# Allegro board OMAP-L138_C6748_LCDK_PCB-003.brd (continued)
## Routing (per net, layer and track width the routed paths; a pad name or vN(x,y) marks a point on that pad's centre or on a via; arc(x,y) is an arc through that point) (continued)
LCD_SDA: length 32.2
  TOP w0.121: U25.4 22.66,60.5 v1(22.86,60.71)
  LYR3 w0.133: P1.15 5.59,68.96 5.59,70.61 6.6,71.63 9.4,71.63 9.91,71.12 11.94,71.12 12.95,70.1 12.95,69.09 15.49,66.55 16.51,66.55 18.8,64.26 22.61,64.26 23.37,63.5 23.37,62.48 23.88,61.98 24.38,61.98 24.64,61.72 24.64,60.45 24.38,60.2 23.37,60.2 v1(22.86,60.71)
LCD_VSYNC/MMCSD1_D4: length 64
  TOP w0.121: U24.6 25.65,62.74 25.91,62.48 v1(26.67,62.48) ; v1(26.67,52.58) 25.91,52.58 25.65,52.84 U15.6
  TOP w0.254: v1(63.76,43.3) U7.G4
  LYR3 w0.133: v1(26.67,52.58) 26.92,52.83 59.94,52.83 v1(62.23,55.12)
  LYR4 w0.121: v1(63.76,43.3) 63.63,43.3 63.36,43.57 63.36,44.31 63.75,44.7 63.75,46.1
  LYR4 w0.133: 63.75,46.1 63.75,47.5 63.25,48.01 63.25,54.1 v1(62.23,55.12) ; v1(26.67,52.58) 26.16,53.09 26.16,61.98 v1(26.67,62.48)
LCD_VSYNC_1V8: length 30
  TOP w0.121: v1(24.13,62.48) 24.64,62.48 25.65,61.47 U24.3
  LYR3 w0.133: P1.17 5.08,69.72 5.08,70.61 6.6,72.14 12.19,72.14 13.21,71.12 13.21,69.34 15.75,66.8 16.76,66.8 19.05,64.52 22.86,64.52 23.62,63.75 23.62,62.99 v1(24.13,62.48)
LCD_VSYNC_5V: length 36.8
  TOP w0.121: v1(24.13,52.58) 24.64,52.58 25.65,51.57 U15.3
  LYR3 w0.133: v1(24.13,52.58) 23.88,52.58 23.37,52.07 23.37,46.74 22.35,45.72 4.83,45.72 3.3,47.24 1.52,47.24 1.02,46.74 1.02,44.2 J8.14
LED3: length 70.2
  TOP w0.121: Q6.2 v1(77.98,40.13)
  TOP w0.254: v1(56.56,32.1) U7.R17
  LYR3 w0.133: v1(57.66,16.51) 58.17,17.02 68.83,17.02 69.6,17.78 v1(82.3,17.78)
  LYR4 w0.121: v1(56.56,32.1) 56.36,32.1 55.63,31.37 55.63,30.1
  LYR4 w0.133: 55.63,30.1 55.63,28.96 55.88,28.7 55.88,25.15 57.66,23.37 v1(57.66,16.51)
  BOTTOM w0.121: v1(82.3,17.78) 82.3,32.51 82.55,32.77 82.55,36.45 78.87,40.13 v1(77.98,40.13) 77.22,40.89 R101.2
LED4: length 77.4
  TOP w0.121: Q6.5 v1(77.98,43.69)
  TOP w0.254: v1(56.56,32.9) U7.R16
  LYR3 w0.133: v1(55.24,16.51) 56.26,17.53 68.33,17.53 69.09,18.29 83.31,18.29 v1(83.82,17.78)
  LYR4 w0.121: 55.36,30.1 55.36,32.37 55.89,32.9 v1(56.56,32.9)
  LYR4 w0.133: 55.36,30.1 55.36,29.33 54.86,28.83 54.86,21.46 55.24,21.08 v1(55.24,16.51)
  BOTTOM w0.121: v1(77.98,43.69) 78.74,42.93 R102.2 79.25,42.42 79.5,42.16 79.5,40.01 82.8,36.7 82.8,18.8 v1(83.82,17.78)
LINKLED: length 14.4
  TOP w0.121: U23.2 v1(72.66,72.37)
  LYR3 w0.133: J13.9 82.68,71.88 73.15,71.88 v1(72.66,72.37)
  BOTTOM w0.121: v1(72.66,72.37) 73.03,72.01 R189.1
MIC_BIAS: length 28.3
  TOP w0.121: v1(12.45,24.89) 12.49,24.94 U22.13
  LYR4 w0.133: v1(12.45,24.89) 13.46,24.89 13.97,24.38 13.97,23.88 14.48,23.37 20.57,23.37 22.35,21.59 22.35,14.48 24.38,12.45 v1(24.38,8.64)
  BOTTOM w0.121: R151.1 v1(24.38,8.64) R150.1
MIC_DET: length 34.3
  TOP w0.121: v1(22.86,11.68) 30.09,11.68 J11.2 ; U22.12 11.77,24.97 v1(11.68,24.89)
  LYR4 w0.133: v1(11.68,24.89) 11.18,24.38 11.18,24 12.57,22.61 19.81,22.61 21.21,21.21 21.21,13.34 v1(22.86,11.68)
  BOTTOM w0.121: v1(22.86,11.68) C175.2 R151.2
MIC_LEFT: length 29.4
  TOP w0.121: U22.11 11.21,26.96 11.05,26.8 11.05,24.77 v1(11.68,24.13)
  LYR4 w0.133: v1(22.86,8.64) C175.1 23.37,10.16 23.37,11.94 21.59,13.72 21.59,21.34 20.07,22.86 12.95,22.86 v1(11.68,24.13)
  BOTTOM w0.121: C175.1 v1(22.86,8.64)
MIC_RIGHT: length 27.8
  TOP w0.121: U22.14 12.99,24.67 v1(12.45,24.13)
  LYR4 w0.133: v1(23.62,8.64) 23.62,9.4 23.88,9.65 23.88,12.19 21.97,14.1 21.97,21.46 20.32,23.11 13.46,23.11 v1(12.45,24.13)
  BOTTOM w0.121: v1(23.62,8.64) 23.62,7.87 23.37,7.62 C173.1
MMCSD0_CLK: length 64.6
  TOP w0.121: v1(67.06,86.36) R47.2
  TOP w0.254: v1(65.36,39.3) U7.E9
  LYR4 w0.133: v1(63.75,71.63) 65.79,73.66 65.79,85.09 v1(67.06,86.36)
  BOTTOM w0.121: v1(67.06,86.36) 67.06,87.38 68.46,88.78 J4.5 ; v1(63.75,71.63) 69.1,66.28 69.1,60.44 70.36,59.18 70.36,52.83 73.74,49.45 73.74,45.04 73.04,44.34 73.04,43.69 72.5,43.15 71.1,43.15 71.01,43.05 70.99,43.05 67.64,39.7 65.73,39.7 65.36,39.33 v1(65.36,39.3)
MMCSD0_CMD: length 65.8
  TOP w0.121: v1(61.21,86.36) R46.2 ; U7.A10 68.58,38.1 68.84,38.36 69.35,38.36 70.61,39.62 72.14,39.62 72.9,40.39 74.42,40.39 v1(74.93,40.89)
  LYR4 w0.133: v1(63.75,74.68) 63.75,83.82 v1(61.21,86.36)
  BOTTOM w0.121: v1(74.93,40.89) 74.53,41.29 74.53,43.14 74.93,43.54 74.93,50.29 72.39,52.83 72.39,60.2 70.61,61.98 70.61,67.82 v1(63.75,74.68) ; J4.3 59.5,88.08 v1(61.21,86.36)
MMCSD0_D0: length 64.8
  TOP w0.121: v1(73.66,40.89) 71.37,40.89 69.22,38.73 68.86,38.73 68.63,38.5 67.76,38.5 U7.B10 ; v1(68.33,86.36) R48.2
  LYR4 w0.133: v1(63.75,73.15) 64.77,74.17 64.77,84.84 66.8,86.87 67.82,86.87 v1(68.33,86.36)
  BOTTOM w0.121: v1(63.75,73.15) 69.85,67.06 69.85,61.21 71.37,59.69 71.37,52.83 74.42,49.78 74.42,43.69 74.06,43.33 74.06,41.29 v1(73.66,40.89) ; v1(68.33,86.36) 69.34,87.38 J4.7
MMCSD0_D1: length 66
  TOP w0.121: v1(73.66,39.62) 73.15,39.12 70.99,39.12 70.1,38.23 70.1,37.72 69.55,37.16 68.75,37.16 68.62,37.3 U7.A11 ; R49.2 v1(69.6,86.36)
  LYR4 w0.133: v1(69.6,86.36) 68.83,87.12 66.29,87.12 64.26,85.09 64.26,74.42 v1(63.75,73.91)
  BOTTOM w0.121: J4.8 69.91,86.68 v1(69.6,86.36) ; v1(63.75,73.91) 70.23,67.44 70.23,61.59 71.88,59.94 71.88,52.83 74.68,50.04 74.68,43.61 74.3,43.23 74.3,40.26 v1(73.66,39.62)
MMCSD0_D2: length 64.2
  TOP w0.121: R45.2 v1(58.67,86.36)
  TOP w0.254: v1(66.96,38.5) U7.C10
  LYR4 w0.133: v1(63.75,72.39) 63.25,72.9 63.25,83.57 60.71,86.11 60.71,86.61 60.45,86.87 59.18,86.87 v1(58.67,86.36)
  BOTTOM w0.121: v1(66.96,38.5) 66.96,38.51 71.25,42.8 72.64,42.8 73.28,43.43 73.79,43.43 74.17,43.81 74.17,49.53 70.87,52.83 70.87,59.44 69.47,60.83 69.47,66.67 v1(63.75,72.39) ; J4.1 57.15,86.68 57.35,86.87 58.17,86.87 v1(58.67,86.36)
MMCSD0_D3: length 62.8
  TOP w0.121: v1(59.94,86.36) R50.2
  TOP w0.254: v1(65.36,36.9) U7.E11
  LYR4 w0.121: 64.96,46.1 64.96,38.25 65.36,37.85 v1(65.36,36.9)
  LYR4 w0.133: v1(59.94,86.36) 59.94,82.04 60.2,81.79 60.96,81.79 61.21,82.04 61.21,83.31 61.47,83.57 62.48,83.57 62.74,83.31 62.74,77.47 61.47,76.2 61.47,72.26 64.26,69.47 64.26,50.04 64.55,49.75 64.55,48.73 64.79,48.49 64.8,48.49 64.96,48.33 64.96,46.1
  BOTTOM w0.121: J4.2 58.93,87.38 v1(59.94,86.36)
MMCSD0_D4: length 64
  TOP w0.121: U7.B11 67.76,36.9 68.95,36.9 68.96,36.92 69.81,36.92 70.36,37.47 70.36,37.97 71.25,38.86 73.66,38.86 74.17,39.37 86.36,39.37 v1(87.12,40.13)
  LYR4 w0.133: J15.5 97.03,62.36 97.03,57.4 96.52,56.9 93.73,56.9 93.47,56.64 93.47,52.07 93.22,51.82 91.06,51.82 90.81,52.07 90.81,56.64 90.55,56.9 88.14,56.9 87.88,56.64 87.88,40.89 v1(87.12,40.13)
MMCSD0_D6: length 61.8
  TOP w0.121: v1(86.36,40.13) 85.85,39.62 74.55,39.62 74.04,40.13 73.15,40.13 72.39,39.37 70.87,39.37 69.61,38.12 69.1,38.12 68.69,37.7 66.96,37.7 U7.C11
  LYR4 w0.133: v1(86.36,40.13) 86.36,41.66 87.63,42.93 87.63,57.15 87.88,57.4 90.81,57.4 91.06,57.15 91.06,52.32 91.31,52.07 92.96,52.07 93.22,52.32 93.22,58.93 93.47,59.18 94.23,59.18 94.49,58.93 94.49,57.53 94.74,57.28 95.63,57.28 95.89,57.53 J15.9
MMCSD0_D7: length 65.6
  TOP w0.121: U7.A12 68.66,36.5 69.09,36.07 69.6,36.07 70.61,37.08 70.61,37.72 71.5,38.61 73.91,38.61 74.42,39.12 86.87,39.12 v1(87.88,40.13)
  LYR4 w0.133: v1(87.88,40.13) 88.14,40.39 88.14,54.36 88.39,54.61 90.3,54.61 90.55,54.36 90.55,44.45 90.81,44.2 93.47,44.2 93.73,44.45 93.73,55.63 93.98,55.88 J15.11
MMCSD1_CLK: length 49.2
  TOP w0.121: U7.G2 63.76,44.9 63.76,45.73 64.77,46.74 68.33,46.74 72.39,50.8 72.39,57.53 75.47,60.61 85.44,60.61 88.9,57.15 92.71,57.15 95.25,54.61 97.16,54.61 98.42,53.34
MMCSD1_CMD: length 47.3
  TOP w0.254: v1(62.16,43.3) U7.J4
  LYR3 w0.121: 63.5,46.1 63.5,44.87 63.13,44.5 62.79,44.5 62.56,44.27 62.56,43.7 v1(62.16,43.3)
  LYR3 w0.133: 98.42,55.88 96.9,54.36 96.9,47.37 96.27,46.74 64.01,46.74 63.5,46.23 63.5,46.1
MMCSD1_D0: length 47.8
  TOP w0.121: U7.G1 63.36,45.83 65.79,48.26 69.09,48.26 72.01,51.18 72.01,57.66 75.31,60.96 85.09,60.96 88.9,64.77 97.16,64.77 98.42,66.04
MMCSD1_D1: length 55.6
  TOP w0.254: v1(62.16,44.1) U7.J3
  LYR3 w0.121: 62.87,46.1 62.56,45.8 62.56,44.73 62.16,44.33 v1(62.16,44.1)
  LYR3 w0.133: 98.42,63.5 99.57,62.36 99.57,60.45 98.81,59.69 95.5,59.69 94.74,58.93 94.74,47.75 93.98,46.99 63.75,46.99 62.87,46.1
MMCSD1_D2: length 53.7
  TOP w0.254: v1(60.56,44.1) U7.K3
  LYR3 w0.121: v1(60.56,44.1) 60.16,44.5 60.16,46.06 60.2,46.1
  LYR3 w0.133: 98.42,60.96 97.41,59.94 95.25,59.94 94.49,59.18 94.49,48.01 93.73,47.24 61.34,47.24 60.2,46.1
MMCSD1_D3: length 52.5
  TOP w0.254: v1(62.96,44.1) U7.H3
  LYR3 w0.121: v1(62.96,44.1) 63.15,44.1 63.88,44.83 63.88,46.1
  LYR3 w0.133: 98.42,58.42 99.57,57.28 99.57,52.83 98.81,52.07 97.79,52.07 97.16,51.44 97.16,45.59 96.27,44.7 88.9,44.7 87.12,46.48 64.26,46.48 63.88,46.1
Net_22: length 0.6
  TOP w0.254: v1(64.56,43.3) 64.16,42.9
Net_207: length 0.6
  TOP w0.254: 35.36,37.3 v1(34.96,36.9)
Net_208: length 0.6
  TOP w0.254: v1(40.56,33.7) 40.16,34.1
Net_209: length 0.6
  TOP w0.254: v1(40.56,36.9) 40.16,37.3
Net_210: length 0.6
  TOP w0.254: v1(39.76,45.7) 39.36,45.3
Net_212: length 0.6
  TOP w0.254: 35.36,34.1 v1(34.96,33.7)
Net_293: length 0.6
  TOP w0.254: v1(66.96,44.9) 66.56,44.5
NMIN: length 6.1
  TOP w0.254: v1(62.16,32.1) U7.J17
  BOTTOM w0.121: R59.2 64.96,29.01 64.96,31.47 64.73,31.7 62.56,31.7 v1(62.16,32.1)
OSCIN: length 7.5
  TOP w0.121: R43.2 v1(60.96,26.16)
  TOP w0.254: v1(60.56,30.5) U7.L19
  BOTTOM w0.121: v1(60.96,26.16) 61.85,27.05 61.85,28.83 61.67,29.01 R264.1 61.37,29.69 v1(60.56,30.5)
PER_IN_MODE: length 3.8
  TOP w0.121: R13.1 R16.2 31.73,66.53 U3.23
PHP_RSTN: length 255.9
  TOP w0.121: v1(72.39,19.56) 72.39,23.5 78.11,29.21 78.11,31.62 76.71,33.02 76.13,33.02 75.88,33.27 U11.4 75.88,35.5 v1(75.95,35.56) ; v1(35.56,29.21) 36.07,29.72 42.42,29.72 43.43,28.7 43.43,25.4 42.42,24.38 42.42,22.61 42.95,22.07 U21.34 46.38,22.07 46.99,21.46 46.99,18.03 48.01,17.02 49.3,17.02 v1(49.8,16.51) ; v1(19.56,30.23) 19.54,30.23 19.3,30.46 U22.33 ; v1(80.01,69.85) 79.49,70.37 U23.19 ; J16.33 v1(68.21,13.46) ; U9.12 60.7,65.79 v1(60.96,65.53) R41.1 ; v1(87.63,67.31) 99.06,67.31 99.57,66.8 99.57,49.4 98.42,48.26 97.16,49.53 87.88,49.53 87.12,50.29 77.98,50.29 v1(77.47,50.8)
  LYR3 w0.133: v1(68.21,13.46) 67.7,12.95 50.42,12.95 49.28,14.1 49.28,15.98 v1(49.8,16.51) ; v1(87.63,67.31) 85.6,67.31 83.06,69.85 v1(80.01,69.85) 78.74,69.85 78.23,69.34 63.25,69.34 60.96,67.06 v1(60.96,65.53) ; v1(19.56,30.23) 20.57,30.23 23.11,27.69 34.54,27.69 34.92,28.07 34.92,28.57 v1(35.56,29.21)
  BOTTOM w0.121: P1.18 0.76,66.67 0.76,57.28 7.62,50.42 7.62,39.62 9.14,38.1 17.02,38.1 17.91,37.21 17.91,31.88 v1(19.56,30.23) ; v1(77.47,50.8) 76.71,50.04 76.71,35.81 76.45,35.56 v1(75.95,35.56) ; v1(72.39,19.56) 72.39,17.64 v1(68.21,13.46) ; v1(49.8,16.51) 51.05,17.76 U27.1
PM_1V2N: length 2.6
  BOTTOM w0.889: JP4.2 40.27,78.74 R5.4
PM_1V2P: length 2.5
  BOTTOM w0.889: JP4.1 40.27,76.2 R5.3
PM_1V8N: length 2.6
  BOTTOM w0.889: JP2.2 40.27,68.58 R2.4
PM_1V8P: length 2.5
  BOTTOM w0.889: R2.3 40.27,66.04 JP2.1
PM_3V3N: length 2.6
  BOTTOM w0.889: R4.4 21.96,76.2 JP3.2
PM_3V3P: length 2.5
  BOTTOM w0.889: R4.3 21.96,78.74 JP3.1
PWR_FAILN: length 9.1
  TOP w0.121: U3.21 30.73,67.57 v1(31.24,67.06)
  LYR4 w0.133: TP9.1 30.23,66.04 v1(31.24,67.06)
  BOTTOM w0.121: R15.2 v1(31.24,67.06)
PWRFAIL_SNS: length 2.6
  TOP w0.121: U3.30 v1(33.78,71.87)
  BOTTOM w0.121: R12.1 R14.2 v1(33.78,71.87)
RTC_CVDD: length 36.3
  TOP w0.254: v1(59.76,35.3) U7.L14
  LYR4 w0.457: 54.36,37.34 52.32,39.37 52.32,51.18 49.28,54.23 49.28,61.21 47.75,62.74 47.75,66.29 v1(48.26,66.8)
  BOTTOM w0.457: v1(48.26,66.8) R29.2 49.53,67.82 R31.1
RTC_VSS: length 18.8
  TOP w0.254: v1(62.96,31.3) U7.H18
  BOTTOM w0.121: v1(62.96,31.3) 63.24,31.02 63.36,30.9 63.36,30.1
  BOTTOM w0.254: C84.2 66.93,23.62 67.18,23.88 67.18,25.4 66.04,26.54 63.75,26.54 63.23,27.07 63.23,29.97 63.36,30.1
  BOTTOM w0.457: C85.2 63.12,23.24 63.12,22.1 63.5,21.72 66.04,21.72 66.55,22.23 C84.2
RTC_XI: length 10
  TOP w0.254: v1(62.16,30.5) U7.J19
  BOTTOM w0.121: v1(62.16,30.5) 62.61,30.05 62.61,26.8 62.99,26.42 62.99,25.4 62.74,25.15 C85.1 62.99,24.38 64.01,24.38 64.64,23.75 Y2.1
RTC_XOUT: length 9.6
  TOP w0.254: v1(62.96,30.5) U7.H19
  BOTTOM w0.121: C84.1 66.55,25.12 66.29,25.37 Y2.2 63.5,25.37 63.25,25.63 63.25,26.54 62.87,26.92 62.87,30.41 v1(62.96,30.5)
RTCK: length 9.4
  TOP w0.121: J6.9 85.09,29.21 83.06,29.21 82.3,28.45 79.25,28.45 78.74,27.94 R269.1
SATA_REF_CLKN: length 16.6
  TOP w0.095: v1(57.4,58.93) 57.65,58.69 57.65,57.65 57.02,57.02 57.02,50.67 58.67,49.02 58.67,45.41 U7.N1
  BOTTOM w0.095: C46.2 57.66,59.94 57.66,59.18 v1(57.4,58.93)
SATA_REF_CLKN_K: length 2.4
  TOP w0.095: U9.5 v1(57.4,62.74)
  BOTTOM w0.095: v1(57.4,62.74) 57.65,62.5 57.65,61.96 C46.1
SATA_REF_CLKP: length 17.5
  TOP w0.095: U7.N2 58.95,44.89 58.95,49.14 57.3,50.79 57.3,56.91 57.92,57.53 57.92,58.69 v1(58.17,58.93)
  BOTTOM w0.095: v1(58.17,58.93) 57.94,59.16 57.94,59.97 C34.2
SATA_REF_CLKP_K: length 2.5
  TOP w0.095: U9.6 57.9,63 v1(58.17,62.74)
  BOTTOM w0.095: v1(58.17,62.74) 57.92,62.5 57.92,61.96 C34.1
SATA_RXN: length 4.5
  TOP w0.095: C92.2 44.86,84.84 44.73,84.96 44.73,85.83 44.25,86.31 44.25,88 J7.5
SATA_RXP: length 4.5
  TOP w0.095: C93.2 44.32,84.84 44.45,84.96 44.45,85.71 43.97,86.19 43.97,88 J7.6
SATA_TXN: length 4.5
  TOP w0.095: J7.3 47.75,88.02 47.75,86.36 47.24,85.85 47.24,84.96 47.12,84.84 C90.2
SATA_TXP: length 4.5
  TOP w0.095: C91.2 47.65,84.84 47.52,84.96 47.52,85.74 48.03,86.24 48.03,87.98 J7.2
SPI0_CLK/EPWM0_A/MII_RXCLK: length 65.6
  TOP w0.121: v1(71.12,64.77) R178.1
  TOP w0.254: v1(66.16,30.5) U7.D19
  LYR4 w0.121: 66.56,30.1 v1(66.16,30.5)
  LYR4 w0.133: 66.56,30.1 66.94,29.72 72.39,29.72 76.96,34.29 78.23,34.29 79.5,35.56 79.5,36.7 81.79,38.99 81.79,40.64 82.55,41.4 82.55,44.7 85.6,47.75 85.6,63.75 83.31,66.04 72.39,66.04 v1(71.12,64.77)
  BOTTOM w0.121: R216.2 v1(71.12,64.77) R178.1
SPI0_ENAN/EPWM0_B/MII_RXDV: length 59.1
  TOP w0.121: v1(83.82,61.47) 84.33,61.98 84.33,71.12 82.55,72.9 82.55,73.66 v1(78.74,77.47) 77.98,76.71 R177.1
  TOP w0.254: v1(66.96,32.1) U7.C17
  LYR4 w0.121: v1(66.96,32.1) 67.36,32.5 68.82,32.5 68.96,32.64
  LYR4 w0.133: v1(83.82,61.47) 83.57,61.21 83.57,48.26 78.99,43.69 78.99,42.67 76.71,40.39 76.71,39.62 72.39,35.31 71.63,35.31 68.96,32.64
  BOTTOM w0.121: v1(78.74,77.47) R217.2
SPI0_SCSN_0/MDIO_D: length 56.5
  TOP w0.121: U23.16 78.67,68.65 v1(78.74,68.58)
  TOP w0.254: v1(66.16,32.1) U7.D17
  LYR3 w0.133: v1(83.82,62.23) 83.82,66.8 81.53,69.09 79.25,69.09 v1(78.74,68.58)
  LYR4 w0.121: v1(66.16,32.1) 66.56,31.7 68.96,31.7
  LYR4 w0.133: v1(83.82,62.23) 84.45,61.59 84.45,60.33 83.82,59.69 83.82,48.01 81.41,45.59 81.41,43.69 79.25,41.53 79.25,38.86 76.45,36.07 74.17,36.07 73.09,34.99 71.82,34.99 69.85,33.02 69.85,32.51 69.04,31.7 68.96,31.7
  BOTTOM w0.121: R169.2 v1(78.74,68.58)
SPI0_SCSN_1/MDIO_CLK: length 51.3
  TOP w0.121: v1(80.01,68.58) 79.22,69.37 U23.17
  TOP w0.254: v1(65.36,32.9) U7.E16
  LYR3 w0.133: v1(82.3,61.47) 82.3,65.28 80.01,67.56 v1(80.01,68.58)
  LYR4 w0.121: v1(65.36,32.9) 65.36,33.1 65.76,33.5 65.76,36.3 66.76,37.29 68.96,37.29
  LYR4 w0.133: 68.96,37.29 69.8,37.29 70.86,38.35 70.87,38.35 72.64,40.13 72.64,40.64 73.41,41.4 75.18,41.4 76.45,42.67 76.45,44.2 76.71,44.45 77.74,44.45 82.3,49.01 v1(82.3,61.47)
  BOTTOM w0.121: R171.2 v1(80.01,68.58)
SPI0_SCSN_2/UART0_RTSN/MII_RXD0: length 47.7
  TOP w0.121: R175.1 v1(76.2,64.77)
  TOP w0.254: v1(66.16,32.9) U7.D16
  LYR4 w0.121: v1(66.16,32.9) 66.39,32.9 66.79,33.3 67.13,33.3 67.36,33.53 67.36,34.09 68.96,35.69
  LYR4 w0.133: v1(76.2,64.77) 77.98,62.99 82.04,62.99 83.06,61.98 83.06,48.77 78.49,44.2 78.49,43.25 72.32,37.08 71.37,37.08 70.1,35.81 69.09,35.81 68.96,35.69
  BOTTOM w0.121: R175.1 v1(76.2,64.77)
SPI0_SCSN_3/UART0_CTSN/MII_RXD1: length 51.5
  TOP w0.121: R174.1 v1(74.93,64.77)
  TOP w0.254: v1(65.36,32.1) U7.E17
  LYR4 w0.121: 68.96,36.91 67.13,36.91 66.56,36.33 66.56,33.53 66.33,33.3 65.99,33.3 65.76,33.07 65.76,32.49 65.37,32.1 v1(65.36,32.1)
  LYR4 w0.133: 68.96,36.91 69.92,36.91 71.62,38.61 73.41,38.61 76.71,41.91 76.71,43.94 76.96,44.2 77.98,44.2 82.8,49.02 82.8,61.72 81.79,62.74 76.96,62.74 v1(74.93,64.77)
  BOTTOM w0.121: R174.1 v1(74.93,64.77)
SPI0_SCSN_4/UART0_TXD/MII_RXD2: length 58
  TOP w0.121: R173.1 v1(73.66,64.77)
  TOP w0.254: v1(66.16,31.3) U7.D18
  LYR4 w0.121: 68.96,31.11 68.75,30.9 66.56,30.9 v1(66.16,31.3)
  LYR4 w0.133: v1(73.66,64.77) 74.17,65.28 77.72,65.28 77.98,65.02 77.98,64.26 78.74,63.5 83.82,63.5 84.84,62.48 84.84,48.51 81.66,45.34 81.66,43.43 79.5,41.27 79.5,38.35 74.68,33.53 71.37,33.53 68.96,31.11
  BOTTOM w0.121: v1(73.66,64.77) R218.2
SPI0_SCSN_5/UART0_RXD/MII_RXD3: length 61.8
  TOP w0.121: R172.1 v1(72.39,64.77)
  TOP w0.254: v1(66.96,30.5) U7.C19
  LYR4 w0.121: v1(66.96,30.5) 67.36,30.1
  LYR4 w0.133: 67.36,30.1 67.49,29.97 69.6,29.97 70.1,30.48 70.1,30.99 71.37,32.26 73.91,32.26 80.52,38.86 80.52,41.78 81.92,43.18 81.92,45.09 85.09,48.26 85.09,62.74 82.55,65.28 79.88,65.28 78.87,64.26 78.49,64.26 78.23,64.52 78.23,65.28 77.98,65.53 73.15,65.53 v1(72.39,64.77)
  BOTTOM w0.121: R172.1 v1(72.39,64.77) R219.2
SPI0_SIMO/EPWM0_SYNCO/MII_CRS: length 53.7
  TOP w0.121: v1(78.74,64.77) R184.1
  TOP w0.254: v1(66.96,31.3) U7.C18
  LYR4 w0.133: v1(72.64,31.7) 73.86,31.7 80.77,38.61 80.77,40.51 82.17,41.91 82.17,44.83 85.34,48.01 85.34,63.25 83.06,65.53 79.5,65.53 v1(78.74,64.77)
  BOTTOM w0.121: v1(72.64,31.7) 72.06,31.11 68.45,31.11 68.24,30.9 67.36,30.9 v1(66.96,31.3) ; R214.2 v1(78.74,64.77)
SPI0_SOMI/EPWM0_SYNCI/MII_RXERR: length 47.6
  TOP w0.121: R179.1 v1(77.47,64.77)
  TOP w0.254: v1(66.96,32.9) U7.C16
  LYR4 w0.121: v1(66.96,32.9) 67.19,32.9 67.59,33.3 68.96,33.3
  LYR4 w0.133: v1(77.47,64.77) 77.47,64.26 78.49,63.25 82.3,63.25 83.31,62.23 83.31,48.51 78.74,43.94 78.74,42.93 76.45,40.64 76.45,39.88 72.14,35.56 71.37,35.56 69.11,33.3 68.96,33.3
  BOTTOM w0.121: R215.2 v1(77.47,64.77) R179.1
SPI1_CLK: length 75
  TOP w0.121: J16.32 v1(67.71,19.56) ; R200.1 v1(15.24,14.99)
  TOP w0.254: v1(63.76,30.5) U7.G19
  LYR3 w0.133: v1(15.24,14.99) 18.41,14.99 25.78,22.35 29.64,22.35 29.65,22.36 30.3,22.36 30.3,22.35 32.29,22.35 32.8,21.84 33.3,21.84 35.46,19.68 42.93,19.68 43.31,20.07 46.48,20.07 47.24,19.3 48.77,19.3 50.16,17.91 64.9,17.91 66.29,19.3 66.29,19.81 66.55,20.07 67.2,20.07 v1(67.71,19.56)
  LYR4 w0.133: v1(67.71,19.56) 67.71,21.92 64.17,25.46 64.17,28.68 63.35,29.49 63.35,29.87 63.76,30.27 v1(63.76,30.5)
SPI1_SCSN_0/EPWM1B: length 48.8
  TOP w0.254: v1(65.36,30.5) U7.E19
  LYR3 w0.121: 64.16,30.1 64.16,31.47 64.39,31.7 64.82,31.7 64.96,31.56 64.96,31.05 65.36,30.65 v1(65.36,30.5)
  LYR3 w0.133: 98.42,15.24 97.03,16.64 97.03,18.29 96.27,19.05 82.8,19.05 82.04,19.81 82.04,25.4 80.26,27.18 71.37,27.18 69.6,28.96 65.28,28.96 64.16,30.07 64.16,30.1
SPI1_SCSN_1/EPWM1A: length 43.7
  TOP w0.254: v1(64.56,31.3) U7.F18
  LYR3 w0.121: 64.96,30.1 64.96,30.48 64.96,30.67 64.56,31.07 v1(64.56,31.3)
  LYR3 w0.133: 98.42,20.32 97.41,19.3 83.06,19.3 82.3,20.07 82.3,25.65 80.52,27.43 71.63,27.43 69.85,29.21 65.53,29.21 64.96,29.78 64.96,30.1
SPI1_SCSN_2/UART1_TXD: length 77
  TOP w0.121: v1(64.96,27.3) 64.32,27.94 58.36,27.94 v1(57.72,27.3)
  TOP w0.254: v1(64.56,30.5) U7.F19
  LYR3 w0.133: v1(57.72,27.3) 57.72,26.73 56.9,25.91 55.88,25.91 55.63,26.16 46.48,26.16 45.97,26.67 42.16,26.67 40.13,28.7 36.58,28.7 36.2,28.32 36.2,27.94 35.43,27.18 28.45,27.18 21.59,20.32 19.3,20.32 15.75,16.76 10.92,16.76 9.4,15.24 9.4,12.7 v1(6.35,9.65)
  LYR4 w0.133: v1(64.56,30.5) 64.56,29.8 64.96,29.4 v1(64.96,27.3)
  BOTTOM w0.121: v1(6.35,9.65) R205.1 R206.1
SPI1_SCSN_3: length 6
  TOP w0.121: J16.34 v1(68.71,19.56)
  BOTTOM w0.121: R208.2 68.71,22.98 v1(68.71,19.56)
SPI1_SCSN_3/UART1_RXD: length 9.9
  TOP w0.254: v1(65.36,31.3) U7.E18
  BOTTOM w0.121: R209.1 R208.1 67.56,25.15 67.56,26.92 66.8,27.69 66.8,29.72 66.42,30.1 65.91,30.1 65.76,30.25 65.76,30.9 v1(65.36,31.3)
SPI1_SCSN_4/UART2_TXD/I2C1_SDA: length 30.5
  TOP w0.121: v1(68.07,25.4) R97.2 67.56,24.64 67.31,24.38 67.31,22.86 72.64,17.53 76.71,17.53 78.99,15.24 78.99,14.22 79.27,13.95 U8.2
  TOP w0.254: v1(64.56,32.9) U7.F16
  BOTTOM w0.121: v1(68.07,25.4) 68.07,26.92 67.03,27.96 67.03,29.81 66.56,30.29 66.56,32.27 66.33,32.5 66.29,32.5 64.96,32.5 v1(64.56,32.9)
SPI1_SCSN_5/UART2_RXD/I2C1_SCL: length 29
  TOP w0.121: v1(69.34,25.4) R96.2 69.85,24.64 70.1,24.38 70.1,20.69 72.76,18.03 79.76,18.03 81.8,15.99 U8.30
  TOP w0.254: v1(64.56,32.1) U7.F17
  LYR4 w0.121: 65.15,30.1 64.96,30.29 64.96,31.31 64.96,31.47 64.56,31.87 v1(64.56,32.1)
  LYR4 w0.133: v1(69.34,25.4) 65.28,29.46 65.28,29.97 65.15,30.1
SPI1_SCSN_6/I2C0_SDA: length 225.6
  TOP w0.121: v1(10.16,35.56) 9.65,35.05 9.65,32.77 10.96,31.46 U22.2 ; v1(43.31,18.29) 43.31,19.18 43.7,19.57 U21.29 ; U16.4 26.47,45.52 v1(26.67,45.72) ; R202.1 v1(12.7,14.99) ; U25.1 20.52,60.5 v1(20.32,60.71) ; J16.30 v1(66.71,19.56)
  TOP w0.254: v1(63.76,31.3) U7.G18
  LYR3 w0.133: v1(43.31,18.29) 34.29,18.29 33.78,18.8 33.78,19.56 33.02,20.32 24.89,20.32 18.54,13.97 13.72,13.97 v1(12.7,14.99) ; v1(26.67,45.72) 26.67,41.66 23.88,38.86 22.1,38.86 21.34,38.1 11.94,38.1 10.67,36.83 10.67,36.07 v1(10.16,35.56) ; v1(66.71,19.56) 67.47,18.8 93.22,18.8 v1(94.23,17.78)
  LYR4 w0.121: v1(63.76,31.3) 63.36,30.9 63.36,30.28
  LYR4 w0.133: v1(10.16,35.56) 9.65,35.05 9.65,26.67 10.67,25.65 10.67,17.02 v1(12.7,14.99) ; v1(26.67,45.72) 25.4,46.99 25.4,58.93 24.13,60.2 20.83,60.2 v1(20.32,60.71) ; 63.36,30.28 62.97,29.89 62.97,29.23 63.25,28.96 63.25,25.65 66.71,22.19 v1(66.71,19.56) ; J15.15 94.49,49.4 94.49,19.81 93.73,19.05 93.73,18.29 v1(94.23,17.78)
  BOTTOM w0.121: v1(66.71,19.56) 66.29,19.14 R89.2 67.06,18.54 67.81,17.79 67.81,13.45 66.55,12.19 48.26,12.19 43.31,17.14 v1(43.31,18.29) 43.31,18.92 42.93,19.3 R146.1
SPI1_SCSN_7/I2C0_SCL: length 237
  TOP w0.121: v1(10.16,36.83) 10.67,36.32 10.67,32.21 10.92,31.96 U22.1 ; v1(20.32,63.25) 20.52,63.45 U25.8 ; U21.28 45.74,19.07 v1(46.23,19.56) ; R201.1 v1(13.97,14.99) ; v1(26.67,48.26) 26.47,48.46 U16.5 ; J16.29 v1(66.21,13.46)
  TOP w0.254: v1(63.76,32.9) U7.G16
  LYR3 w0.133: v1(13.97,14.99) 14.48,14.48 18.54,14.48 26.04,21.97 29.8,21.97 29.8,21.98 30.14,21.98 30.15,21.97 32.13,21.97 32.64,21.46 33.15,21.46 34.92,19.68 34.92,18.8 35.18,18.54 42.55,18.54 43.56,19.56 v1(46.23,19.56) ; v1(26.67,48.26) 25.91,47.5 25.91,41.53 24.26,39.88 21.34,39.88 19.81,38.35 11.68,38.35 v1(10.16,36.83) ; v1(66.21,13.46) 69.89,17.14 86.74,17.14 87.38,16.51 93.73,16.51 v1(94.23,17.02)
  LYR4 w0.121: v1(63.76,32.9) 63.36,32.5 63.36,31.93 63.13,31.7 62.76,31.7 62.56,31.5 62.56,31.13 62.56,30.33
  LYR4 w0.133: v1(20.32,63.25) 21.59,61.98 24.64,61.98 25.91,60.71 25.91,49.02 v1(26.67,48.26) ; J15.13 94.23,51.69 94.23,20.07 93.47,19.3 93.47,17.78 v1(94.23,17.02) ; v1(10.16,36.83) 9.4,36.07 9.4,26.42 10.41,25.4 10.41,16.76 11.94,15.24 11.94,14.73 12.19,14.48 13.46,14.48 v1(13.97,14.99) ; v1(66.21,13.46) 66.21,15.32 65.12,16.42 65.12,23.28 62.93,25.46 62.93,28.77 62.56,29.13 62.56,30.33
  BOTTOM w0.121: v1(46.23,19.56) 46.99,18.8 46.99,14.22 48.51,12.7 65.45,12.7 v1(66.21,13.46) 66.21,14.39 R86.2 R147.2
SPI1_SIMO: length 88.8
  TOP w0.121: U26.D4 12.19,9.11 v1(12.19,12.19) ; J16.36 v1(69.71,19.56)
  TOP w0.254: v1(63.76,32.1) U7.G17
  LYR3 w0.133: v1(12.19,12.19) 11.94,12.45 11.94,15.25 12.19,15.49 18.29,15.49 25.55,22.76 34.01,22.76 34.92,21.84 34.92,21.35 35.19,21.08 46.61,21.08 48.01,19.68 49.15,19.68 50.55,18.29 64.26,18.29 65.28,19.3 65.28,19.81 66.04,20.57 68.69,20.57 v1(69.71,19.56)
  LYR4 w0.121: v1(63.76,32.1) 64.16,31.7 64.16,30.27
  LYR4 w0.133: 64.16,30.27 64.16,29.87 64.55,29.48 64.55,25.62 69.71,20.46 v1(69.71,19.56)
SPI1_SOMI: length 88.1
  TOP w0.121: R204.1 v1(11.43,14.99) ; J16.31 v1(67.21,13.46)
  TOP w0.254: v1(62.96,32.1) U7.H17
  LYR3 w0.133: v1(11.43,14.99) 11.43,15.49 11.94,16 18.29,16 25.4,23.11 34.29,23.11 35.31,22.1 48.51,22.1 49.53,21.08 49.53,20.07 51.05,18.54 63.5,18.54 64.26,19.3 64.26,20.13 v1(64.71,20.57)
  LYR4 w0.121: v1(62.96,32.1) U7.H17 61.98,32.5
  LYR4 w0.133: v1(67.21,13.46) 66.75,13 65.86,13 65.62,13.25 65.62,15.16 64.26,16.51 64.26,20.13 v1(64.71,20.57) 64.71,23.17 62.61,25.27 62.61,28.57 61.72,29.46 61.72,32.25 61.97,32.5 61.98,32.5
SPIO_CLK: length 43.3
  TOP w0.121: v1(93.47,40.39) 95.76,38.1 J15.25
  BOTTOM w0.121: v1(93.47,40.39) 93.47,53.85 92.71,54.61 87.38,54.61 80.61,61.37 72.23,61.37 71.12,62.48 R216.1
SPIO_ENAN: length 57
  BOTTOM w0.121: J15.27 97.41,37.08 97.41,69.22 96.27,70.36 84.58,70.36 82.55,72.39 82.55,73.91 81.53,74.93 v1(78.74,74.93) R217.1
SPIO_SIMO: length 36.2
  BOTTOM w0.121: R214.1 84.84,62.99 87.88,59.94 96.27,59.94 96.9,59.31 96.9,44.2 J15.21
SPIO_SOMI: length 37.7
  BOTTOM w0.121: R215.1 77.47,62.48 77.72,62.23 79.25,62.23 79.76,62.74 84.58,62.74 87.63,59.69 92.71,59.69 94.74,57.66 94.74,41.78 J15.23
TCK: length 29
  TOP w0.121: v1(77.47,26.16) 77.47,27.94 78.42,28.89 79.69,28.89 80.01,29.21 R58.2 R271.1
  TOP w0.254: v1(62.16,33.7) U7.J15
  LYR3 w0.121: 61.85,30.1 61.72,30.23 61.72,33.26 v1(62.16,33.7)
  LYR3 w0.133: v1(77.47,26.16) 65.02,26.16 64.26,26.92 64.26,27.69 61.85,30.1
TCT_RCT: length 9.7
  BOTTOM w0.457: J13.3 87.63,82.04 88.27,82.68 R185.1 C198.1 90.81,82.68 91.44,82.04 91.44,80.64
TDI: length 43.2
  TOP w0.121: R55.2 v1(81.28,24.13) 85.09,24.13 J6.3
  TOP w0.254: v1(58.96,32.9) U7.M16
  LYR3 w0.133: v1(63.75,20.57) 64.26,21.08 69.09,21.08 69.85,20.32 73.15,20.32 73.66,20.83 80.01,20.83 80.64,21.46 80.64,23.5 v1(81.28,24.13)
  BOTTOM w0.121: v1(58.96,32.9) 59.36,32.5 59.36,31.93 59.6,31.7 61.01,31.7 61.72,30.99 61.72,30.35 62.23,29.84 62.23,26.8 62.61,26.42 62.61,25.53 62.23,25.15 62.23,23.24 62.61,22.86 62.61,21.72 v1(63.75,20.57)
TDO: length 8
  TOP w0.121: R272.1 80.01,27.62 80.33,27.94 82.23,27.94 83.5,26.67 85.09,26.67 J6.7
TMS: length 35.6
  TOP w0.121: J6.1 85.09,21.59 83.06,21.59 82.3,20.83 80.77,20.83 v1(80.01,21.59) R57.2
  TOP w0.254: v1(59.76,32.9) U7.L16
  LYR3 w0.121: v1(59.76,32.9) 60.16,32.5 60.97,32.5 61.47,32 61.47,30.61
  LYR3 w0.133: v1(80.01,21.59) 78.49,23.11 70.36,23.11 68.83,24.64 65.79,24.64 61.47,28.96 61.47,30.61
TRSTN: length 32.1
  TOP w0.121: J6.2 80.01,20.32 v1(78.74,21.59) R61.1
  TOP w0.254: v1(59.76,32.1) U7.L17
  LYR3 w0.121: v1(59.76,32.1) 59.97,32.1 60.38,31.7 60.76,31.7 60.96,31.5 60.96,30.1
  LYR3 w0.133: v1(78.74,21.59) 76.2,21.59 75.18,22.61 69.34,22.61 68.33,23.62 65.79,23.62 60.95,28.45 60.95,30.09 60.96,30.1
TS_INT: length 24.8
  TOP w0.121: U28.3 14.69,60.71 v1(15.49,60.71)
  LYR4 w0.133: v1(15.49,60.71) 15.49,61.72 10.92,66.29 10.92,71.12 v1(10.41,71.63)
  BOTTOM w0.121: P2.12 6.1,66.55 6.1,70.87 6.86,71.63 v1(10.41,71.63)
TXD0_K: length 4.6
  TOP w0.254: v1(64.56,44.1) U7.F3
  BOTTOM w0.121: R90.1 62.56,45.9 64.36,44.1 v1(64.56,44.1)
TXD1_K: length 3.9
  TOP w0.254: v1(65.36,45.7) U7.E1
  BOTTOM w0.121: R93.1 63.76,45.84 64.3,45.3 U7.E1 v1(65.36,45.7)
TXD2_K: length 3.4
  TOP w0.254: v1(65.36,44.9) U7.E2
  BOTTOM w0.121: v1(65.36,44.9) 65.36,45.13 65.79,45.56 65.79,45.85 64.96,46.67 R92.1
TXD3_K: length 4
  TOP w0.254: v1(65.36,44.1) U7.E3
  BOTTOM w0.121: R91.1 66.16,45.59 65.76,45.19 65.76,44.5 v1(65.36,44.1)
UART0_RX: length 51
  BOTTOM w0.121: J15.31 94.49,31.88 94.49,41.02 94.23,41.27 94.23,55.63 92.71,57.15 85.34,57.15 80.77,61.72 73.15,61.72 72.39,62.48 R219.1
UART0_TX: length 47.5
  BOTTOM w0.121: R218.1 73.66,62.48 74.17,61.98 81.03,61.98 85.6,57.4 92.96,57.4 94.49,55.88 94.49,41.53 94.74,41.27 94.74,34.16 J15.29
UART1_RXD: length 58.6
  TOP w0.121: v1(73.41,19.56) 73.91,19.05 93.73,19.05 v1(94.23,18.54)
  LYR4 w0.133: J15.17 94.74,47.12 94.74,19.05 v1(94.23,18.54)
  BOTTOM w0.121: v1(73.41,19.56) 73.41,21.08 71.63,22.86 69.6,22.86 69.34,23.11 R209.2
UART1_TXD: length 132.9
  TOP w0.121: J15.19 94.61,46.99 89.15,46.99 86.87,49.28 v1(86.87,49.78)
  LYR3 w0.133: v1(86.87,49.78) 77.6,49.78 75.06,52.32 31.24,52.32 27.43,48.51 27.43,41.78 24.26,38.61 22.48,38.61 21.72,37.85 13.97,37.85 13.21,37.08 13.21,36.58 11.68,35.05 9.4,35.05 v1(8.89,35.56)
  LYR4 w0.133: v1(9.91,7.62) 8.89,8.64 8.89,15.49 10.16,16.76 10.16,25.15 8.89,26.42 v1(8.89,35.56)
  BOTTOM w0.121: R206.2 9.14,8.38 v1(9.91,7.62)
USB0_DN: length 113.8
  TOP w0.114: v1(31.37,44.89) 31.16,44.68 30.5,44.68 30,45.19 30,54.37 31,55.37 37.35,55.37 38.22,56.24 45.06,56.24 46.38,57.56 46.38,61.57 44.98,62.97 44.98,79.87 43.04,81.81 31.1,81.81 30.38,82.53 30.38,83.05 30.65,83.31 J2.2
  TOP w0.254: v1(58.96,31.3) U7.M18
  LYR3 w0.121: v1(58.96,31.3) 58.56,30.9 58.56,30.32 58.36,30.12 58.36,30.1
  LYR3 w0.127: 58.36,30.1 58.22,29.96 58.22,29.44 56.85,28.07 50.67,28.07 50.08,27.47 49.4,27.47 48.81,28.07 45.77,28.07 43.58,30.25 35.58,30.25 34.98,30.86 33.66,30.86 32.13,32.38 32.13,44.13 v1(31.37,44.89)
USB0_DP: length 113.7
  TOP w0.114: v1(31.37,44.2) 31.16,44.4 30.39,44.4 29.72,45.07 29.72,54.48 30.89,55.65 37.24,55.65 38.1,56.52 44.94,56.52 46.1,57.67 46.1,61.45 44.7,62.85 44.7,79.76 42.93,81.53 30.99,81.53 30.11,82.42 30.11,83.05 29.84,83.31 J2.3
  TOP w0.254: U7.M19 v1(58.96,30.5)
  LYR3 w0.121: 58.79,30.1 58.96,30.27 v1(58.96,30.5)
  LYR3 w0.127: v1(31.37,44.2) 31.62,44.2 31.83,43.99 31.83,32.26 33.53,30.56 34.85,30.56 35.45,29.95 43.46,29.95 45.64,27.76 48.68,27.76 49.28,27.17 50.2,27.17 50.8,27.76 56.97,27.76 58.52,29.31 58.52,29.83 58.66,29.97 58.66,29.99 58.76,30.09 58.78,30.09 58.79,30.1
USB0_ID: length 85.9
  TOP w0.121: v1(44.7,58.93) 45.21,59.44 45.21,61.47 44.2,62.48 44.2,79.5 42.67,81.03 30.73,81.03 29.46,82.3 29.46,82.64 v1(29.04,83.06) ; v1(29.04,83.06) 28.03,82.04 22.1,82.04 21.08,83.06 21.08,84.96 JP1.2 ; v1(29.04,83.06) J2.4
  TOP w0.254: v1(57.36,32.9) U7.P16
  LYR4 w0.121: v1(57.36,32.9) 57.36,33.57 56.83,34.1 54.67,34.1 53.76,35.01
  LYR4 w0.133: 53.76,35.01 51.31,37.47 51.31,50.16 47.24,54.23 47.24,57.28 45.59,58.93 v1(44.7,58.93)
USB1_DN: length 34.5
  TOP w0.254: v1(57.36,31.3) U7.P18
  LYR4 w0.121: v1(57.36,31.3) 57.36,31.07 56.96,30.67 56.96,30.23
  LYR4 w0.127: 56.96,30.23 56.96,29.48 58.17,28.27 58.17,27 59.18,25.98 59.18,21.41 59.39,21.21 59.39,15.42 60.2,14.61 60.2,13.03 61.09,12.14 69.77,12.14 71.22,10.69 71.22,9.74 J5.2
USB1_DP: length 33.6
  TOP w0.254: v1(57.36,30.5) U7.P19
  LYR4 w0.127: v1(57.36,30.5) 57.36,30.1 57.26,30.01 57.26,29.6 58.47,28.4 58.47,27.13 59.49,26.11 59.49,21.54 59.69,21.34 59.69,15.54 60.5,14.73 60.5,13.16 61.21,12.45 69.9,12.45 71.53,10.82 71.53,9.74 J5.3
USB_DRVVBUSN: length 69.4
  TOP w0.121: v1(47.75,59.94) 47.75,61.72 45.72,63.75 45.72,80.52 43.69,82.55 41.66,82.55 v1(41.15,83.06) R52.1 R51.2
  TOP w0.254: v1(60.56,31.3) U7.K18
  LYR4 w0.121: v1(60.56,31.3) 60.16,31.7 60.16,32.27 59.93,32.5 59.59,32.5 59.36,32.73 59.36,33.98 58.44,34.9 57.99,34.9 57.76,35.13 57.76,35.47 57.53,35.7 54.6,35.7 53.76,36.54
  LYR4 w0.133: 53.76,36.54 51.82,38.48 51.82,50.67 48.26,54.23 48.26,59.44 v1(47.75,59.94)
  BOTTOM w0.121: U6.2 39.24,84.2 39.62,83.82 40.89,83.82 41.15,83.57 v1(41.15,83.06)
USB_UART_DN: length 9.7
  TOP w0.114: U8.15 83.8,9.65 84.07,9.38 84.07,9.22 84,9.14 83.66,9.14 83.58,9.07 83.58,5.08 83.83,4.83 85.33,4.83 85.45,4.94 85.45,5.08 85.32,5.21 85,5.21 84.92,5.28 J3.2
USB_UART_DP: length 9.8
  TOP w0.114: J3.3 85.72,4.83 85.45,4.55 83.72,4.55 83.3,4.96 U8.14
VDCDC1: length 2.7
  BOTTOM w0.457: v1(24.64,74.3) v1(23.69,74.3) R4.2
VDCDC2: length 1.8
  BOTTOM w0.457: R2.1 v1(38.57,64.14)
  vias: v1(37.59,64.14)
VDCDC3: length 4.8
  BOTTOM w0.457: R5.1 v1(38.57,74.3) v1(37.59,74.3) 36.96,73.66 R6.2
VDECODE_CLKOUT: length 18.7
  TOP w0.121: v1(46.99,24.64) 46.56,25.07 U21.40
  BOTTOM w0.121: R141.1 55.63,14.48 55.37,14.73 55.37,15.75 54.61,16.51 53.59,16.51 53.34,16.76 U27.2 53.34,18.67 52.96,19.05 50.55,19.05 49.53,20.07 49.53,20.95 46.99,23.5 v1(46.99,24.64)
VPIF_CLKIN1: length 13.2
  TOP w0.121: U7.V15 54.16,34.5 53.54,34.5 51.66,32.62 51.66,28.8 48.26,25.4 R81.1
VPIF_DOUT0/LCD_D_0: length 35.3
  TOP w0.121: U7.W1 53.38,45.3 51.69,46.99 51.69,48.39 50.16,49.91 48.9,49.91 48.77,50.04 48.77,55.12 48.64,55.24 47.24,55.24 47.12,55.12 47.12,52.7 46.99,52.58 45.09,52.58 44.96,52.45 44.96,50.67 44.83,50.55 32.98,50.55 32.85,50.67 U14.2
VPIF_DOUT1/LCD_D_1: length 37.2
  TOP w0.121: U14.3 33.35,53.65 33.02,53.98 33.02,54.23 32.7,54.55 32.19,54.55 31.62,53.98 31.62,50.8 32.38,50.04 46.86,50.04 46.99,50.16 46.99,50.42 46.86,50.55 45.59,50.55 45.47,50.67 45.47,50.93 45.59,51.05 48.13,51.05 48.26,50.93 48.26,49.53 48.39,49.4 49.91,49.4 51.18,48.13 51.18,46.74 53.42,44.5 U7.W2
VPIF_DOUT2/LCD_D_2: length 35.6
  TOP w0.121: U14.5 34.35,53.59 34.04,53.91 34.04,54.78 33.76,55.05 31.94,55.05 31.11,54.23 31.11,50.55 32.13,49.53 47.5,49.53 48.13,48.9 49.66,48.9 50.67,47.88 50.67,46.48 53.47,43.69 53.75,43.69 U7.W3
VPIF_DOUT3/LCD_D_3: length 34.9
  TOP w0.121: U7.V1 54.14,45.72 53.34,45.72 51.94,47.12 51.94,48.51 50.29,50.16 49.15,50.16 49.02,50.29 49.02,55.37 48.9,55.5 46.99,55.5 46.86,55.37 46.86,52.96 46.74,52.83 44.83,52.83 44.7,52.7 44.7,50.93 44.58,50.8 34.42,50.8 34.29,50.93 34.29,51.44 34.42,51.56 34.72,51.56 34.85,51.69 U14.6
VPIF_DOUT4/LCD_D_4: length 37.6
  TOP w0.121: v1(34.54,54.1) 35.05,54.61 35.43,54.61 35.85,54.19 U14.8 ; U7.V2 54.16,44.9 53.4,44.9 51.44,46.86 51.44,48.26 50.04,49.66 48.64,49.66 48.51,49.78 48.51,51.18 48.39,51.31 45.34,51.31 45.21,51.18 45.21,50.42 45.09,50.29 32.51,50.29 31.88,50.93 31.88,53.85 32.13,54.1 v1(32.38,54.1)
  BOTTOM w0.121: v1(34.54,54.1) 34.04,53.59 32.89,53.59 v1(32.38,54.1)
VPIF_DOUT5/LCD_D_5: length 37.9
  TOP w0.121: v1(34.54,54.86) 35.56,54.86 36.35,54.07 U14.9 ; U7.V3 54.16,44.1 53.44,44.1 50.93,46.61 50.93,48.01 49.78,49.15 48.26,49.15 47.62,49.78 32.26,49.78 31.37,50.67 31.37,54.1 32.07,54.8 32.83,54.8 v1(33.53,54.1)
  BOTTOM w0.121: v1(34.54,54.86) 34.29,54.86 v1(33.53,54.1)
VPIF_DOUT6/LCD_D_6: length 34.8
  TOP w0.121: U7.U1 55.36,45.99 50.67,50.67 49.91,50.67 49.53,51.05 49.53,55.88 49.4,56.01 46.48,56.01 46.35,55.88 46.35,53.47 46.23,53.34 44.7,53.34 44.58,53.47 v1(44.58,54.1) ; U14.11 37.35,53.73 v1(37.72,54.1)
  BOTTOM w0.121: v1(44.58,54.1) 44.58,51.82 44.32,51.56 37.97,51.56 37.72,51.82 v1(37.72,54.1)
VPIF_DOUT7/LCD_D_7: length 36.3
  TOP w0.121: U7.U2 54.96,44.9 54.96,45.62 54.61,45.96 53.48,45.96 52.2,47.24 52.2,48.64 50.42,50.42 49.4,50.42 49.28,50.55 49.28,55.63 49.15,55.75 46.74,55.75 46.61,55.63 46.61,53.21 46.48,53.09 44.58,53.09 44.45,52.96 44.45,51.18 44.32,51.05 35.94,51.05 35.81,51.18 35.81,51.44 35.94,51.56 37.72,51.56 37.85,51.69 37.85,52.7 U14.12
VPIF_DOUT8/LCD_D_8: length 37.2
  TOP w0.121: U14.13 38.35,54.6 v1(38.61,54.86)
  TOP w0.254: v1(54.96,44.1) U7.U3
  LYR3 w0.133: v1(50.04,55.12) 49.53,55.63 45.21,55.63 44.96,55.88 36.45,55.88 36.32,55.75 36.32,54.99 36.45,54.86 v1(38.61,54.86)
  LYR4 w0.121: 55.88,46.1 55.88,45.02 v1(54.96,44.1)
  LYR4 w0.133: 55.88,46.1 56.39,46.61 56.39,50.04 52.32,54.1 51.05,54.1 v1(50.04,55.12)
  BOTTOM w0.121: R263.2 R85.2 v1(38.61,54.86)
VPIF_DOUT9/LCD_D_9: length 37.6
  TOP w0.121: v1(45.59,56.13) 45.28,55.82 40.32,55.82 38.85,54.34 U14.14 ; v1(57.36,49.66) 56.9,49.19 56.9,46.99 56.11,46.2 56.11,45.35 U7.T1 ; v1(59.76,49.66) 59.76,49.71 58.67,50.8 58.67,51.94 SW1.4 v1(58.42,54.36)
  LYR3 w0.133: v1(45.59,56.13) 46.23,56.13 46.48,56.39 56.39,56.39 v1(58.42,54.36) ; v1(59.76,49.66) v1(57.36,49.66)
  BOTTOM w0.121: v1(58.42,54.36) 57.15,55.63 R80.2
VPIF_DOUT10/LCD_D_10: length 36.9
  TOP w0.121: U14.16 39.85,54.84 40.58,55.56 45.4,55.56 45.59,55.37 v1(45.59,54.1) ; U7.T2 55.76,44.9 55.76,45.35 55.76,46.35 56.64,47.24 56.64,48.01 56.39,48.26 54.61,48.26 54.36,48.51 54.36,50.04 54.61,50.29 55.63,50.29 55.88,50.55 SW1.3 55.88,53.72 56.3,54.14 56.3,54.7 v1(55.88,55.12)
  LYR3 w0.133: v1(55.88,55.12) 55.44,54.67 55.44,53.91 55.12,53.59 45.72,53.59 45.59,53.72 v1(45.59,54.1)
  BOTTOM w0.121: v1(55.88,55.12) R74.2
VPIF_DOUT11/LCD_D_11: length 37.2
  TOP w0.121: v1(53.34,54.36) SW1.2 ; U14.17 40.35,53.63 40.13,53.85 40.13,54.36 v1(40.64,54.86)
  TOP w0.254: v1(55.76,44.1) U7.T3
  LYR3 w0.133: v1(53.34,54.36) 52.83,53.85 46.74,53.85 45.97,54.61 45.34,54.61 45.09,54.36 45.09,53.85 44.83,53.59 38.99,53.59 38.86,53.72 38.86,54.36 39.37,54.86 v1(40.64,54.86)
  LYR4 w0.133: v1(53.34,54.36) 53.34,53.59 56.64,50.29 56.64,46.46 56.15,45.97 56.15,44.49 v1(55.76,44.1)
  BOTTOM w0.121: R73.1 v1(53.34,54.36)
VPIF_DOUT12/LCD_D_12: length 37.6
  TOP w0.121: SW1.1 v1(50.8,55.12) 49.66,56.26 46.23,56.26 46.1,56.13 46.1,53.85 45.85,53.59 45.34,53.59 45.09,53.85 45.09,54.74 44.51,55.31 41.85,55.31 41.35,54.81 U14.19
  TOP w0.254: v1(56.56,45.7) U7.R1
  LYR4 w0.133: v1(56.56,45.7) 56.9,46.04 56.9,50.55 53.85,53.59 53.85,54.61 53.59,54.86 53.59,56.52 53.47,56.64 52.2,56.64 52.07,56.52 52.07,54.74 51.94,54.61 51.31,54.61 v1(50.8,55.12)
  BOTTOM w0.121: R75.1 v1(50.8,55.12)
VPIF_DOUT13/LCD_D_13: length 36.9
  TOP w0.121: v1(42.16,54.1) 41.85,53.79 U14.20
  TOP w0.254: v1(56.56,44.9) U7.R2
  LYR3 w0.133: v1(54.1,55.12) 54.1,55.5 54.23,55.63 55.75,55.63 55.88,55.75 55.88,56.01 55.75,56.13 52.2,56.13 52.07,56.01 52.07,54.48 51.94,54.36 47.24,54.36 46.48,55.12 44.7,55.12 44.45,55.37 43.05,55.37 42.93,55.24 42.93,54.23 42.8,54.1 v1(42.16,54.1)
  LYR4 w0.121: 57.53,46.1 56.56,45.13 v1(56.56,44.9)
  LYR4 w0.133: v1(54.1,55.12) 54.1,53.85 57.78,50.16 57.78,46.35 57.53,46.1
  BOTTOM w0.121: v1(42.16,54.1) 42.67,54.61 R82.2 R252.2
VPIF_DOUT14/LCD_D_14: length 36.8
  TOP w0.121: U14.22 42.85,54.18 v1(42.16,54.86)
  TOP w0.254: v1(56.56,44.1) U7.R3
  LYR3 w0.133: v1(51.56,55.12) 51.05,54.61 47.5,54.61 46.74,55.37 44.96,55.37 44.7,55.63 42.29,55.63 42.16,55.5 v1(42.16,54.86)
  LYR4 w0.121: 58,46.1 56.96,45.07 56.96,44.5 v1(56.56,44.1)
  LYR4 w0.133: 58,46.1 58.17,46.27 58.17,50.29 54.55,53.91 54.55,57.02 54.42,57.15 51.69,57.15 51.56,57.02 v1(51.56,55.12)
  BOTTOM w0.121: R261.2 R83.2 41.78,54.86 v1(42.16,54.86)
VPIF_DOUT15/LCD_D_15: length 36
  TOP w0.121: U14.23 43.35,54.19 42.95,54.59 42.95,54.86 43.07,54.99 43.69,54.99 v1(43.81,54.86)
  TOP w0.254: v1(57.36,43.3) U7.P4
  LYR3 w0.133: v1(54.99,54.36) 54.99,53.98 54.86,53.85 53.98,53.85 53.85,53.98 53.85,54.61 53.59,54.86 53.59,55.75 53.47,55.88 52.45,55.88 52.32,55.75 52.32,55.58 52.4,55.5 53.14,55.5 53.21,55.42 53.21,55.19 53.14,55.12 52.4,55.12 52.32,55.04 52.32,54.23 52.2,54.1 46.99,54.1 46.23,54.86 v1(43.81,54.86)
  LYR4 w0.121: 58.55,46.1 58.55,45.21 57.76,44.43 57.76,43.7 v1(57.36,43.3)
  LYR4 w0.133: v1(54.99,54.36) 54.99,53.98 58.55,50.42 58.55,46.1
  BOTTOM w0.121: v1(43.81,54.86) 43.69,54.99 R262.2 R84.2
VS/BLK/GPIO: length 17.7
  TOP w0.121: U21.73 v1(29.99,19.07)
  LYR4 w0.133: TP13.1 33.27,30.48 30.99,30.48 29.21,28.7 29.21,19.85 v1(29.99,19.07)
XTAL1: length 23.8
  TOP w0.121: v1(29.97,20.83) 29.46,20.32 29.46,18.88 29.77,18.57 U21.74 ; v1(26.67,34.04) Y4.1
  BOTTOM w0.121: v1(29.97,20.83) 29.97,20.82 28.96,20.82 28.7,21.08 28.7,22.1 28.45,22.35 R142.1 C142.1 26.92,23.62 26.67,23.88 v1(26.67,34.04)
XTAL2: length 6.3
  TOP w0.121: v1(29.97,18.03) 30.01,18.07 U21.75
  BOTTOM w0.121: R142.2 R144.2 28.96,19.81 29.46,19.3 29.46,18.54 v1(29.97,18.03)
N16780199: length 11.5
  TOP w0.121: v1(18.29,43.94) 18.76,44.41 U13.47
  LYR4 w0.133: v1(18.29,43.94) 19.05,44.7 v1(19.05,52.07)
  BOTTOM w0.121: R113.1 18.29,52.29 18.51,52.07 v1(19.05,52.07)
N16780460: length 10.5
  TOP w0.121: v1(19.56,43.94) 19.26,44.24 U13.48
  BOTTOM w0.121: R114.1 v1(19.56,43.94)
N16782098: length 2.7
  TOP w0.121: U13.25 11.47,52.28 v1(10.92,52.83)
  BOTTOM w0.121: R99.1 v1(10.92,52.83)
N16782372: length 2.9
  TOP w0.121: v1(13.46,55.12) 13.76,54.82 U13.24
  BOTTOM w0.121: R98.1 v1(13.46,55.12)
N16792303: length 11.7
  TOP w0.121: v1(14.51,43.94) 14.76,44.2 U13.39
  LYR3 w0.133: v1(14.51,43.94) 14.51,44.45 14.76,44.7 21.34,44.7 v1(22.1,43.94)
  BOTTOM w0.121: v1(22.1,43.94) 22.86,44.7 C107.2
N16794587: length 3.5
  TOP w0.121: U13.37 13.17,45.43 12.7,44.96 v1(12.7,43.94)
  BOTTOM w0.121: v1(12.7,43.94) C116.2
N16803294: length 3.1
  TOP w0.121: v1(13.72,43.94) 14.26,44.49 U13.38
  BOTTOM w0.121: R117.1 13.97,44.2 v1(13.72,43.94)
N16951647: length 10.1
  TOP w0.254: U21.5 35.35,14.69 35.05,14.99 v1(34.8,14.99) 34.85,14.93 U21.4
  TOP w0.457: v1(32.77,18.54) 33.53,17.78 33.53,16.26 v1(34.8,14.99)
  BOTTOM w0.457: FB9.2 34.8,15.56 v1(34.8,14.99) C148.1 ; C147.1 v1(32.77,18.54)
N16958510: length 29.9
  TOP w0.254: U21.11 38.35,14.86 38.48,14.99 v1(38.86,14.99) 38.85,14.97 U21.12 ; 43.31,17.4 43.48,17.57 U21.25 ; U21.76 30.52,17.57 29.97,17.02 v1(29.97,16.76) 30.17,16.57 U21.78
  TOP w0.457: v1(40.64,16) 41.91,16 43.31,17.4
  LYR3 w0.457: v1(40.64,16) 39.88,16 v1(38.86,14.99) 37.08,16.76 v1(29.97,16.76)
  BOTTOM w0.457: v1(29.97,16.76) 30.99,17.78 C157.1 ; FB10.2 41.85,16 v1(40.64,16) 39.37,16 38.86,15.49 v1(38.86,14.99) C158.1
N16963689: length 2.4
  TOP w0.121: U21.1 33.35,12.78 33.02,12.45 v1(32.77,12.45)
  BOTTOM w0.121: C160.1 v1(32.77,12.45)
N16963693: length 1.4
  TOP w0.121: U21.80 31.5,15.24 v1(31.75,14.99)
  BOTTOM w0.121: C159.1 v1(31.75,14.99)
N16963722: length 2.1
  TOP w0.121: U21.2 33.85,12.51 v1(33.78,12.45)
  BOTTOM w0.121: C161.1 v1(33.78,12.45)
N16970911: length 2.1
  TOP w0.121: U21.18 41.85,12.51 v1(41.91,12.45)
  BOTTOM w0.121: C168.1 v1(41.91,12.45)
N16970913: length 2.4
  TOP w0.121: U21.17 41.35,12.65 41.15,12.45 v1(40.89,12.45)
  BOTTOM w0.121: C167.1 v1(40.89,12.45)
N16970940: length 2.9
  TOP w0.121: v1(46.23,16.51) 46.17,16.57 U21.23
  BOTTOM w0.121: C169.1 45.97,16.76 v1(46.23,16.51)
N16971321: length 2.9
  TOP w0.121: v1(39.88,14.99) 40.64,14.99 40.85,14.78 U21.16
  BOTTOM w0.121: C166.1 v1(39.88,14.99)
N16980937: length 2.4
  TOP w0.121: v1(37.85,14.99) 37.59,14.99 37.35,14.74 U21.9
  BOTTOM w0.121: C165.1 v1(37.85,14.99)
N16980978: length 2.4
  TOP w0.121: U21.7 36.35,12.73 36.07,12.45 v1(35.81,12.45)
  BOTTOM w0.121: v1(35.81,12.45) C164.1
N16984417: length 2
  TOP w0.121: U21.8 v1(36.85,14.97)
  BOTTOM w0.121: C162.2 36.83,14.95 v1(36.85,14.97)
N16987290: length 21.8
  LYR3 w0.133: v1(51.75,10.16) 51.56,10.16 48.51,13.21 37.59,13.21 v1(36.83,12.45)
  BOTTOM w0.121: FB11.2 53.53,9.84 C163.1 53.09,9.4 R273.1 v1(51.75,10.16) ; C162.1 v1(36.83,12.45)
N16998043: length 5.7
  TOP w0.121: Y4.2 v1(26.67,17.78)
  BOTTOM w0.121: R144.1 C143.1 v1(26.67,17.78)
N17013995: length 2.6
  TOP w0.121: v1(43.31,21.57) U21.33
  BOTTOM w0.121: R143.2 43.94,21.34 43.69,21.59 43.33,21.59 v1(43.31,21.57)
N17016505: length 6.8
  TOP w0.121: U21.71 33.09,20.07 33.53,20.51 33.53,23.11 v1(33.02,23.62)
  BOTTOM w0.121: R145.2 v1(33.02,23.62)
N17141238: length 2.4
  TOP w0.121: R163.2 v1(20.57,28.19)
  BOTTOM w0.121: v1(20.57,28.19) R163.2 Y5.1
N17232839: length 15
  TOP w0.121: U22.35 19.59,31.46 20.57,30.48 22.86,30.48 23.37,30.99 23.37,35.05 24.89,36.58 26.92,36.58 TP16.1
N17232859: length 11.6
  TOP w0.121: U22.34 19.59,30.96 20.32,30.23 23.11,30.23 23.62,30.73 23.62,34.8 24.38,35.56 TP17.1
N17232911: length 37.7
  TOP w0.121: v1(22.86,15.49) 23.37,16 23.37,23.62 19.68,27.3 19.68,29.08 19.31,29.46 U22.31
  LYR4 w0.133: v1(38.1,4.32) 37.59,4.83 34.04,4.83 24.89,13.97 23.88,13.97 22.86,14.99 v1(22.86,15.49)
  BOTTOM w0.121: C179.1 v1(38.1,4.32)
N17232927: length 38.5
  TOP w0.121: v1(22.86,16.26) 22.86,23.62 19.43,27.05 19.43,28.33 19.3,28.46 U22.29
  LYR4 w0.133: v1(22.86,16.26) 23.37,15.75 23.37,14.99 23.88,14.48 24.89,14.48 34.29,5.08 39.88,5.08 v1(40.64,4.32)
  BOTTOM w0.121: C178.1 v1(40.64,4.32)
N17232971: length 3.7
  TOP w0.121: U22.46 13.49,33.27 12.98,33.78 12.19,33.78 11.43,34.54 R158.2
N17232975: length 2.9
  TOP w0.121: U22.45 13.99,33.25 12.7,34.54 R159.2
N17235121: length 3.2
  TOP w0.121: U22.43 14.99,34.04 v1(15.24,34.29) R162.2
  BOTTOM w0.121: v1(15.24,34.29) R162.2
N17236450: length 3
  BOTTOM w0.121: R154.1 R155.2 C177.2 C176.1
N17236452: length 3
  BOTTOM w0.121: C172.1 C174.2 R153.2 R152.1
N17236454: length 42.7
  TOP w0.121: v1(10.67,30.73) 10.89,30.96 U22.3
  LYR4 w0.133: v1(38.86,11.43) 38.35,10.92 36.58,10.92 36.07,11.43 29.21,11.43 23.11,17.53 23.11,22.61 19.3,26.42 12.95,26.42 12.19,27.18 12.19,29.21 v1(10.67,30.73)
  BOTTOM w0.121: C172.2 v1(38.86,11.43)
N17236480: length 43.5
  TOP w0.121: U22.5 10.91,29.96 v1(10.67,29.72)
  LYR4 w0.133: v1(10.67,29.72) 11.94,28.45 11.94,26.92 12.7,26.16 19.05,26.16 22.73,22.48 22.73,17.4 29.21,10.92 35.81,10.92 36.32,10.41 38.86,10.41 v1(39.88,11.43)
  BOTTOM w0.121: C176.2 v1(39.88,11.43)
N17236488: length 3.2
  BOTTOM w0.121: J10.3 34.26,10.67 R152.2
N17236492: length 3.2
  BOTTOM w0.121: R154.2 44.48,10.67 J10.2
N17245158: length 2.8
  TOP w0.121: R182.2 80.52,70.36 80.01,70.87 U23.20
N17245537: length 3.3
  TOP w0.121: U23.14 76.95,68.08 77.47,67.56 78.23,67.56 78.74,67.06 R184.2
N17245539: length 2.4
  TOP w0.121: R175.2 75.45,67.3 U23.11
N17245582: length 2.5
  TOP w0.121: R179.2 77.47,67.06 76.45,68.08 U23.13
N17245602: length 4.9
  TOP w0.121: R178.2 71.12,67.31 72.64,68.83 72.64,69.6 72.92,69.87 U23.7
N17245638: length 3.2
  TOP w0.121: R173.2 v1(73.66,67.31) 74.45,68.1 U23.9
  BOTTOM w0.121: R173.2 v1(73.66,67.31)
N17245640: length 2.5
  TOP w0.121: R177.2 77.98,75.18 77.98,74.68 77.45,74.15 U23.26
N17245742: length 4.1
  TOP w0.121: R183.2 80.01,67.06 79.25,67.82 77.72,67.82 77.45,68.09 U23.15
N17245758: length 2.1
  TOP w0.121: R174.2 74.95,66.57 U23.10
N17245773: length 3.7
  TOP w0.121: U23.8 73.15,69.37 73.03,69.24 73.03,67.18 R172.2
N17258283: length 1.8
  TOP w0.254: U17.K9 v1(34.16,41.7)
  BOTTOM w0.121: R125.1 33.76,42.1 v1(34.16,41.7)
N17393106: length 4.2
  TOP w0.121: v1(71.12,68.58) R190.2 68.85,69.34 Y6.2
  BOTTOM w0.121: v1(71.12,68.58) R190.2
N17400815: length 2.4
  TOP w0.121: R186.1 73.66,74.93 74.45,74.14 U23.32
N17544407: length 2.1
  TOP w0.121: v1(7.37,75.44) 7.35,75.45 D3.2
  BOTTOM w0.121: R9.2 6.6,75.44 v1(7.37,75.44)
N17548747: length 16.1
  TOP w0.121: S1.2 55.32,80.72 55.88,81.28 57.91,81.28 59.05,80.14 U1.1
  BOTTOM w0.121: S1.2 S1.1
N17650320: length 14.6
  TOP w0.254: v1(58.16,44.1) U7.N3
  LYR4 w0.121: v1(58.16,44.1) 58.93,44.87 58.93,46.1
  LYR4 w0.133: v1(54.99,55.12) 55.44,54.67 55.44,54.04 58.93,50.55 58.93,46.1
  BOTTOM w0.121: v1(54.99,55.12) 54.99,55.63 C26.1
N17656359: length 6
  TOP w0.254: v1(58.16,32.9) U7.N17
  BOTTOM w0.121: C25.1 60.16,30.67 59.93,30.9 58.79,30.9 58.56,31.13 U7.N17 v1(58.16,32.9)
N17906579: length 1.4
  TOP w0.254: U18.C3 v1(81.76,52.5)
  BOTTOM w0.121: v1(81.76,52.5) 81.76,51.81 R139.1
N18123385: length 2.9
  TOP w0.254: v1(67.76,45.7) U7.B1
  BOTTOM w0.121: v1(67.76,45.7) 67.76,45.7 R95.1
N18123387: length 3
  TOP w0.254: v1(67.76,44.9) U7.B2
  BOTTOM w0.121: R94.1 70.05,44.5 69.34,44.5 68.94,44.9 v1(67.76,44.9)
N18208208: length 67.4
  TOP w0.121: v1(47.75,58.93) 47.24,59.44 47.24,61.72 45.47,63.5 45.47,80.26 43.43,82.3 39.62,82.3 39.37,82.55 C83.1 38.93,83.82 R54.1
  TOP w0.254: v1(58.16,30.5) U7.N19
  LYR4 w0.121: 53.76,35.78 54.63,34.9 56.54,34.9 57.76,33.68 57.76,32.66 57.92,32.5 58.33,32.5 58.56,32.27 U7.N19 v1(58.16,30.5)
  LYR4 w0.133: v1(47.75,58.93) 47.75,54.23 51.56,50.42 51.56,37.97 53.76,35.78
N18472217: length 16.5
  TOP w0.121: U23.6 v1(72.66,70.37)
  LYR3 w0.133: TP18.1 84.57,70.37 v1(72.66,70.37)
  BOTTOM w0.121: C144.1 73.65,70.37 v1(72.66,70.37)
N18511755: length 4.9
  TOP w0.121: U23.18 79.23,69.87 80.01,69.09 80.26,69.09 80.52,68.83 80.52,67.31 R187.2
N18783117: length 2.9
  TOP w0.121: R36.2 60.96,68.58 60.71,68.33 60.71,67.82 60.18,67.29 U9.15
N18784485: length 2.2
  TOP w0.121: U9.13 60.7,66.29 60.96,66.55 R35.2
N18785856: length 2.4
  TOP w0.121: R34.2 60.96,64.52 60.19,65.29 U9.11
N18803276: length 3.7
  TOP w0.121: v1(53.72,65.28) 53.72,67.04 53.98,67.29 U9.26
  BOTTOM w0.121: R37.1 v1(53.72,65.28)
N18804657: length 1.9
  TOP w0.121: v1(53.72,67.82) 54.65,67.82 U9.25
  BOTTOM w0.121: v1(53.72,67.82) R38.1
N18806041: length 2.4
  TOP w0.121: R39.1 60.96,67.56 60.19,66.79 U9.14
N18807428: length 2.9
  TOP w0.121: R40.1 60.96,63.5 60.71,63.75 60.71,64.26 60.18,64.79 U9.10
N18880116: length 6
  TOP w0.121: 55.64,70.59 56.9,69.34 U9.21 ; 55.64,70.59 57.13,70.59 57.91,71.37 C47.1 ; 55.64,70.59 Y1.2
N18892363: length 5.5
  TOP w0.121: U9.17 58.9,69.31 59.69,70.1 61.72,70.1 62.23,70.61 C48.2
N18895224: length 4.1
  TOP w0.121: C49.2 59.69,70.61 59.18,70.1 58.42,70.1 57.9,69.58 U9.19
N20179308: length 2.2
  TOP w0.121: U11.3 77.22,31.77 77.47,31.52 R65.2
N22409494: length 6.2
  TOP w0.121: J6.11 85.09,31.75 81.53,31.75 81.28,31.5 R271.2
N22965999: length 1.9
  BOTTOM w0.457: R31.2 BH1.1
N24724105: length 10.6
  TOP w0.121: U7.T18 55.76,31.3 55.76,29.72 56.01,29.47 56.01,24.64 54.36,22.99 R60.2
N24803967: length 1.8
  BOTTOM w0.121: R176.2 86.74,73.41 J13.10
N24819875: length 26.9
  BOTTOM w1.016: J13.14 97.79,84.45 97.79,88.39 96.52,89.66 R180.2 82.55,89.66 81.28,88.39 81.28,84.45 J13.13
N25060845: length 3
  TOP w0.121: J9.2 v1(55.37,6.86)
  BOTTOM w0.121: FB11.1 v1(55.37,6.86)
N26098709: length 2.6
  TOP w0.121: U3.18 29.23,66.06 R10.1
N26107809: length 1.6
  TOP w0.254: 29.73,75.18 U3.6
N26126911: length 1.1
  TOP w0.254: U3.27 34.02,70.37
N26141295: length 1.6
  TOP w0.254: U3.3 31.23,75.18
N26148986: length 4
  TOP w0.121: v1(34.8,71.88) 33.81,72.87 U3.32
  BOTTOM w0.121: v1(34.8,71.88) R8.1 R6.1
N26169371: length 6.4
  TOP w0.254: U3.13 28.96,70.87 v2(29.21,71.12) ; v2(31.75,72.39) 31.77,72.37 U3.31
  TOP w0.457: FB1.2 37.27,72.9 v1(36.58,72.9) v1(36.58,71.88) 37.27,71.88 FB1.2
  vias: v2(29.21,72.39) v2(29.21,69.85) v2(30.48,72.39) v2(30.48,71.12) v2(30.48,69.85) v2(31.75,71.12) v2(31.75,69.85)
N26269870: length 5.7
  BOTTOM w0.121: U6.4 40.19,81.92 40.07,81.79 35.69,81.79 35.56,81.66 U4.9
N26409188: length 4.3
  TOP w0.121: v1(34.8,70.87) 34.29,71.37 U3.29
  BOTTOM w0.121: v1(34.8,70.87) 34.29,71.37 R3.2
N26417389: length 2.8
  TOP w0.121: U3.17 28.73,67.34 28.19,66.8 R11.1
N26426042: length 2.6
  TOP w0.121: U3.24 32.23,66.07 R7.1
N26578476: length 4
  TOP w0.121: Q3.3 15.75,67.06 v1(16.26,67.56) 16.7,68.01 Q1.1
  BOTTOM w0.121: R24.1 v1(16.26,67.56)
N26578488: length 2.2
  TOP w0.121: v1(11.94,67.82) 12.13,68.01 Q3.1
  BOTTOM w0.121: v1(11.94,67.82) 12.19,67.56 R27.2
N26585213: length 4
  TOP w0.121: Q2.1 16.7,71.82 v1(16.26,71.37) 15.75,70.87 Q4.3
  BOTTOM w0.121: R26.1 v1(16.26,71.37)
